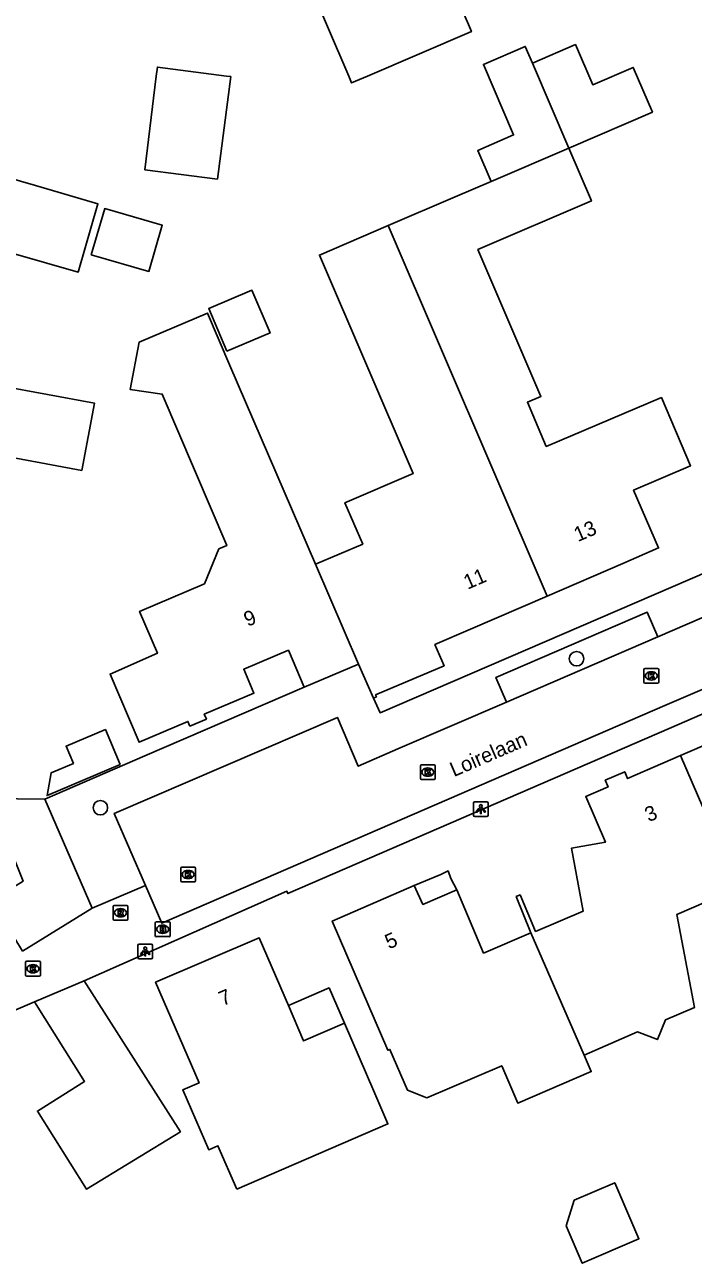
# Model space of a CAD drawing. Extents: x 157767 to 159171, y 387842 to 389425.
# Drawn here: x 158081 to 158126.1, y 388669.8 to 388753.5 of the extents above; entities that cross this region are included whole.
import ezdxf

# ---------------------------------------------------------------- set-up
doc = ezdxf.new("R2010")
doc.units = 0
for name, color, linetype in [('IMGEO_Boom', 7, 'Continuous'), ('IMGEO_Brandkraan', 7, 'Continuous'), ('IMGEO_Kolk', 7, 'Continuous'), ('IMGEO_Lichtpunt', 7, 'Continuous'), ('IMGEO_Openbare_ruimte_label', 7, 'Continuous'), ('IMGEO_Pand', 7, 'Continuous'), ('IMGEO_Pand_nummerreeks', 7, 'Continuous'), ('IMGEO_Pand_overbouw', 7, 'Continuous'), ('IMGEO_Rijbaan_lokaal_open', 7, 'Continuous'), ('IMGEO_Rioolput', 7, 'Continuous'), ('IMGEO_Voetpad_open', 7, 'Continuous')]:
    doc.layers.add(name, color=color, linetype=linetype)

msp = doc.modelspace()

# ---------------------------------------------------------------- linework, layer by layer
at = {"layer": 'IMGEO_Boom'}
for centre in [(158118.262, 388710.655), (158086.105, 388700.597)]:
    msp.add_circle(centre, 0.489, dxfattribs=at)
at = {"layer": 'IMGEO_Brandkraan'}
for p, q in [((158089.813, 388691.961), (158089.813, 388692.813)), ((158089.888, 388692.887), (158090.74, 388692.887)), ((158090.324, 388692.107), (158090.299, 388692.107)), ((158090.301, 388692.667), (158090.326, 388692.667)), ((158090.814, 388692.813), (158090.814, 388691.961)), ((158090.74, 388691.887), (158089.888, 388691.887))]:
    msp.add_line(p, q, dxfattribs=at)
for points in [[(158089.813, 388691.961), (158089.813, 388692.813)], [(158089.888, 388692.887), (158090.74, 388692.887)], [(158090.161, 388692.587), (158090.161, 388692.187), (158090.374, 388692.187)], [(158090.392, 388692.587), (158090.161, 388692.587)], [(158090.34, 388692.506), (158090.286, 388692.506), (158090.286, 388692.43)], [(158090.286, 388692.43), (158090.339, 388692.43)], [(158090.348, 388692.354), (158090.286, 388692.354), (158090.286, 388692.273)], [(158090.286, 388692.273), (158090.348, 388692.273)], [(158090.814, 388692.813), (158090.814, 388691.961)], [(158090.74, 388691.887), (158089.888, 388691.887)]]:
    msp.add_lwpolyline(points, dxfattribs=at)
for centre, radius, start, end in [((158089.89, 388692.811), 0.0765, 91.55205, 178.44795), ((158089.89, 388692.811), 0.0765, 91.55205, 178.44795), ((158090.341, 388692.468), 0.0379, 267.82845, 90.93552), ((158090.349, 388692.313), 0.0404, 269.87594, 90.50774), ((158090.38, 388692.438), 0.251, 268.66757, 293.53466), ((158090.396, 388692.442), 0.145, 59.4692, 91.53667), ((158090.421, 388692.489), 0.0922, 285.51372, 58.15012), ((158090.426, 388692.297), 0.105, 301.31148, 78.98903), ((158090.738, 388692.811), 0.0765, 1.55205, 88.44795), ((158090.738, 388692.811), 0.0765, 1.55205, 88.44795), ((158089.89, 388691.963), 0.0765, 181.55205, 268.44795), ((158089.89, 388691.963), 0.0765, 181.55205, 268.44795), ((158090.738, 388691.963), 0.0765, 271.55205, 358.44795), ((158090.738, 388691.963), 0.0765, 271.55205, 358.44795)]:
    msp.add_arc(centre, radius, start, end, dxfattribs=at)
for centre, major_axis, ratio, start_param, end_param in [((158090.3, 388692.387), (-0.387, 0.002), 0.722429, 4.712389, 7.853982), ((158090.325, 388692.387), (-0.39, 0.002), 0.717154, 1.570796, 4.712389)]:
    msp.add_ellipse(centre, major_axis=major_axis, ratio=ratio, start_param=start_param, end_param=end_param, dxfattribs=at)
at = {"layer": 'IMGEO_Kolk'}
for p, q in [((158122.81, 388709.072), (158122.81, 388709.924)), ((158122.885, 388709.998), (158123.737, 388709.998)), ((158123.298, 388709.778), (158123.323, 388709.778)), ((158123.811, 388709.924), (158123.811, 388709.072)), ((158123.737, 388708.998), (158122.885, 388708.998)), ((158123.321, 388709.218), (158123.296, 388709.218)), ((158107.713, 388702.572), (158107.713, 388703.424)), ((158107.788, 388703.498), (158108.64, 388703.498)), ((158108.201, 388703.278), (158108.226, 388703.278)), ((158108.714, 388703.424), (158108.714, 388702.572)), ((158108.64, 388702.498), (158107.788, 388702.498)), ((158108.224, 388702.718), (158108.199, 388702.718)), ((158091.526, 388695.66), (158091.526, 388696.512)), ((158091.601, 388696.586), (158092.453, 388696.586)), ((158092.014, 388696.366), (158092.039, 388696.366)), ((158092.527, 388696.512), (158092.527, 388695.66)), ((158092.453, 388695.586), (158091.601, 388695.586)), ((158092.037, 388695.806), (158092.012, 388695.806)), ((158081.053, 388689.296), (158081.053, 388690.148)), ((158081.128, 388690.222), (158081.98, 388690.222)), ((158081.541, 388690.002), (158081.566, 388690.002)), ((158082.054, 388690.148), (158082.054, 388689.296)), ((158081.98, 388689.222), (158081.128, 388689.222)), ((158081.564, 388689.442), (158081.539, 388689.442))]:
    msp.add_line(p, q, dxfattribs=at)
for points in [[(158122.81, 388709.072), (158122.81, 388709.924)], [(158122.885, 388709.998), (158123.737, 388709.998)], [(158123.131, 388709.698), (158123.254, 388709.698), (158123.254, 388709.547), (158123.384, 388709.698), (158123.548, 388709.698), (158123.402, 388709.547), (158123.555, 388709.298), (158123.403, 388709.298), (158123.318, 388709.462), (158123.254, 388709.395), (158123.254, 388709.298), (158123.131, 388709.298), (158123.131, 388709.698)], [(158123.811, 388709.924), (158123.811, 388709.072)], [(158123.737, 388708.998), (158122.885, 388708.998)], [(158107.713, 388702.572), (158107.713, 388703.424)], [(158107.788, 388703.498), (158108.64, 388703.498)], [(158108.034, 388703.198), (158108.157, 388703.198), (158108.157, 388703.047), (158108.287, 388703.198), (158108.451, 388703.198), (158108.305, 388703.047), (158108.458, 388702.798), (158108.306, 388702.798), (158108.221, 388702.962), (158108.157, 388702.895), (158108.157, 388702.798), (158108.034, 388702.798), (158108.034, 388703.198)], [(158108.714, 388703.424), (158108.714, 388702.572)], [(158108.64, 388702.498), (158107.788, 388702.498)], [(158091.526, 388695.66), (158091.526, 388696.512)], [(158091.601, 388696.586), (158092.453, 388696.586)], [(158091.847, 388696.286), (158091.97, 388696.286), (158091.97, 388696.135), (158092.1, 388696.286), (158092.264, 388696.286), (158092.118, 388696.135), (158092.271, 388695.886), (158092.119, 388695.886), (158092.034, 388696.05), (158091.97, 388695.983), (158091.97, 388695.886), (158091.847, 388695.886), (158091.847, 388696.286)], [(158092.527, 388696.512), (158092.527, 388695.66)], [(158092.453, 388695.586), (158091.601, 388695.586)], [(158081.053, 388689.296), (158081.053, 388690.148)], [(158081.128, 388690.222), (158081.98, 388690.222)], [(158081.374, 388689.922), (158081.497, 388689.922), (158081.497, 388689.771), (158081.627, 388689.922), (158081.791, 388689.922), (158081.645, 388689.771), (158081.798, 388689.522), (158081.646, 388689.522), (158081.561, 388689.686), (158081.497, 388689.619), (158081.497, 388689.522), (158081.374, 388689.522), (158081.374, 388689.922)], [(158082.054, 388690.148), (158082.054, 388689.296)], [(158081.98, 388689.222), (158081.128, 388689.222)]]:
    msp.add_lwpolyline(points, dxfattribs=at)
for centre, start, end in [((158122.887, 388709.922), 91.55205, 178.44795), ((158122.887, 388709.922), 91.55205, 178.44795), ((158123.735, 388709.922), 1.55205, 88.44795), ((158123.735, 388709.922), 1.55205, 88.44795), ((158122.887, 388709.074), 181.55205, 268.44795), ((158122.887, 388709.074), 181.55205, 268.44795), ((158123.735, 388709.074), 271.55205, 358.44795), ((158123.735, 388709.074), 271.55205, 358.44795), ((158107.79, 388703.422), 91.55205, 178.44795), ((158107.79, 388703.422), 91.55205, 178.44795), ((158108.638, 388703.422), 1.55205, 88.44795), ((158108.638, 388703.422), 1.55205, 88.44795), ((158107.79, 388702.574), 181.55205, 268.44795), ((158107.79, 388702.574), 181.55205, 268.44795), ((158108.638, 388702.574), 271.55205, 358.44795), ((158108.638, 388702.574), 271.55205, 358.44795), ((158091.603, 388696.51), 91.55205, 178.44795), ((158091.603, 388696.51), 91.55205, 178.44795), ((158092.451, 388696.51), 1.55205, 88.44795), ((158092.451, 388696.51), 1.55205, 88.44795), ((158091.603, 388695.662), 181.55205, 268.44795), ((158091.603, 388695.662), 181.55205, 268.44795), ((158092.451, 388695.662), 271.55205, 358.44795), ((158092.451, 388695.662), 271.55205, 358.44795), ((158081.13, 388690.146), 91.55205, 178.44795), ((158081.13, 388690.146), 91.55205, 178.44795), ((158081.978, 388690.146), 1.55205, 88.44795), ((158081.978, 388690.146), 1.55205, 88.44795), ((158081.13, 388689.298), 181.55205, 268.44795), ((158081.13, 388689.298), 181.55205, 268.44795), ((158081.978, 388689.298), 271.55205, 358.44795), ((158081.978, 388689.298), 271.55205, 358.44795)]:
    msp.add_arc(centre, 0.0765, start, end, dxfattribs=at)
for centre, major_axis, ratio, start_param, end_param in [((158123.297, 388709.498), (-0.387, 0.002), 0.722429, 4.712389, 7.853982), ((158123.322, 388709.498), (-0.39, 0.002), 0.717154, 1.570796, 4.712389), ((158108.2, 388702.998), (-0.387, 0.002), 0.722429, 4.712389, 7.853982), ((158108.225, 388702.998), (-0.39, 0.002), 0.717154, 1.570796, 4.712389), ((158092.013, 388696.086), (-0.387, 0.002), 0.722429, 4.712389, 7.853982), ((158092.038, 388696.086), (-0.39, 0.002), 0.717154, 1.570796, 4.712389), ((158081.54, 388689.722), (-0.387, 0.002), 0.722429, 4.712389, 7.853982), ((158081.565, 388689.722), (-0.39, 0.002), 0.717154, 1.570796, 4.712389)]:
    msp.add_ellipse(centre, major_axis=major_axis, ratio=ratio, start_param=start_param, end_param=end_param, dxfattribs=at)
at = {"layer": 'IMGEO_Lichtpunt'}
for p, q in [((158111.297, 388700.905), (158111.297, 388700.098)), ((158111.297, 388700.905), (158111.297, 388700.098)), ((158112.199, 388701), (158111.391, 388701)), ((158112.199, 388701), (158111.391, 388701)), ((158112.293, 388700.098), (158112.293, 388700.905)), ((158112.293, 388700.098), (158112.293, 388700.905)), ((158111.391, 388700.004), (158112.199, 388700.004)), ((158111.391, 388700.004), (158112.199, 388700.004)), ((158088.635, 388691.293), (158088.635, 388690.486)), ((158088.635, 388691.293), (158088.635, 388690.486)), ((158089.537, 388691.388), (158088.729, 388691.388)), ((158089.537, 388691.388), (158088.729, 388691.388)), ((158089.631, 388690.486), (158089.631, 388691.293)), ((158089.631, 388690.486), (158089.631, 388691.293)), ((158088.729, 388690.392), (158089.537, 388690.392)), ((158088.729, 388690.392), (158089.537, 388690.392))]:
    msp.add_line(p, q, dxfattribs=at)
for points in [[(158111.671, 388700.569), (158111.71, 388700.541), (158111.522, 388700.279), (158111.484, 388700.306), (158111.671, 388700.569)], [(158111.773, 388700.521), (158111.82, 388700.521), (158111.82, 388700.199), (158111.773, 388700.199), (158111.773, 388700.521)], [(158111.883, 388700.541), (158111.921, 388700.568), (158112.108, 388700.306), (158112.069, 388700.278), (158111.883, 388700.541)], [(158089.009, 388690.957), (158089.048, 388690.929), (158088.86, 388690.667), (158088.822, 388690.694), (158089.009, 388690.957)], [(158089.111, 388690.909), (158089.158, 388690.909), (158089.158, 388690.587), (158089.111, 388690.587), (158089.111, 388690.909)], [(158089.221, 388690.929), (158089.259, 388690.956), (158089.446, 388690.694), (158089.407, 388690.666), (158089.221, 388690.929)]]:
    msp.add_lwpolyline(points, dxfattribs=at)
for centre in [(158111.796, 388700.703), (158089.134, 388691.091)]:
    msp.add_circle(centre, 0.0994, dxfattribs=at)
for centre, start, end in [((158111.391, 388700.905), 90, 180), ((158111.391, 388700.905), 90, 180), ((158112.199, 388700.905), 0, 90), ((158112.199, 388700.905), 0, 90), ((158111.391, 388700.098), 180, 270), ((158111.391, 388700.098), 180, 270), ((158112.199, 388700.098), 270, 0), ((158112.199, 388700.098), 270, 360), ((158088.729, 388691.293), 90, 180), ((158088.729, 388691.293), 90, 180), ((158089.537, 388691.293), 0, 90), ((158089.537, 388691.293), 0, 90), ((158088.729, 388690.486), 180, 270), ((158088.729, 388690.486), 180, 270), ((158089.537, 388690.486), 270, 0), ((158089.537, 388690.486), 270, 360)]:
    msp.add_arc(centre, 0.0946, start, end, dxfattribs=at)
at = {"layer": 'IMGEO_Pand'}
for points in [[(158102.873, 388750), (158100.069, 388756.563), (158098.104, 388761.16), (158106.19, 388764.627), (158108.155, 388760.03), (158111.161, 388752.999), (158104.146, 388750), (158103.07, 388749.54), (158102.873, 388750)], [(158112.491, 388742.885), (158111.59, 388744.985), (158114.013, 388746.025), (158111.968, 388750.789), (158114.793, 388752.001), (158115.277, 388750.873)], [(158117.739, 388745.138), (158123.389, 388747.563), (158122.092, 388750.584), (158119.355, 388749.409), (158118.19, 388752.124), (158115.277, 388750.873)], [(158094.007, 388743.039), (158089.104, 388743.671), (158089.878, 388750), (158089.952, 388750.606), (158094.628, 388750), (158094.906, 388749.964), (158094.007, 388743.039)], [(158115.277, 388750.873), (158117.739, 388745.138)], [(158075.789, 388744.331), (158081.72, 388742.6), (158085.94, 388741.382), (158084.606, 388736.762), (158080.38, 388737.98), (158073.565, 388739.944), (158071.86, 388734.03), (158067.254, 388735.368), (158062.452, 388736.763), (158064.588, 388744.125), (158069.289, 388742.786), (158070.191, 388745.965)], [(158117.739, 388745.138), (158119.269, 388741.573), (158111.6, 388738.281), (158115.856, 388728.369), (158114.939, 388727.976), (158116.218, 388724.995), (158123.988, 388728.285), (158125.961, 388723.69), (158122.118, 388722.028), (158123.799, 388718.137), (158121.38, 388717.092), (158116.266, 388714.882)], [(158112.491, 388742.885), (158117.739, 388745.138)], [(158105.536, 388739.9), (158110.07, 388741.846), (158112.491, 388742.885)], [(158085.492, 388737.926), (158086.394, 388741.049), (158090.278, 388739.928), (158089.376, 388736.804), (158085.492, 388737.926)], [(158100.638, 388717.032), (158103.821, 388718.399), (158102.623, 388721.188), (158107.223, 388723.163), (158100.895, 388737.907), (158105.536, 388739.9)], [(158116.266, 388714.882), (158105.536, 388739.9)], [(158094.649, 388731.415), (158093.42, 388734.302), (158096.332, 388735.542), (158097.562, 388732.655), (158094.649, 388731.415)], [(158099.864, 388708.724), (158098.797, 388711.231), (158095.786, 388709.949), (158096.472, 388708.336), (158093.121, 388706.91), (158093.26, 388706.584), (158092.145, 388706.11), (158092.013, 388706.419), (158088.715, 388705.015), (158086.757, 388709.616), (158089.955, 388711.021), (158088.752, 388713.848), (158093.135, 388715.713), (158094.113, 388718.07), (158094.636, 388718.293), (158090.283, 388728.521), (158088.117, 388728.826), (158088.715, 388732.029), (158093.346, 388734), (158094.851, 388730.465), (158100.638, 388717.032)], [(158084.862, 388723.375), (158074.95, 388725.205), (158074.636, 388723.504), (158072.511, 388723.897), (158072.164, 388721.947), (158070.4, 388722.259), (158069.578, 388717.73), (158063.701, 388718.771), (158058.777, 388719.644), (158059.718, 388725.009), (158059.233, 388725.097), (158059.43, 388726.184), (158059.91, 388726.139), (158060.281, 388728.104), (158064.478, 388727.37), (158068.338, 388726.695), (158068.912, 388729.966), (158073.83, 388729.06), (158075.984, 388728.664), (158076.171, 388729.677), (158085.7, 388727.918), (158084.862, 388723.375)], [(158100.638, 388717.032), (158103.54, 388710.289)], [(158116.266, 388714.882), (158111.105, 388712.651), (158108.695, 388711.61), (158109.311, 388710.185), (158104.688, 388708.207), (158104.74, 388708.086), (158104.538, 388707.998)], [(158103.54, 388710.289), (158099.864, 388708.724)], [(158104.538, 388707.998), (158103.54, 388710.289)], [(158125.29, 388704.111), (158131.722, 388706.892), (158133.025, 388703.88), (158134.76, 388705.224), (158137.384, 388701.72), (158138.161, 388702.047), (158141.725, 388693.793), (158137.134, 388691.813), (158137.012, 388691.76), (158133.205, 388696.905), (158129.155, 388695.158)], [(158087.445, 388703.511), (158082.505, 388701.409), (158082.778, 388702.948), (158084.28, 388703.587), (158083.789, 388704.741), (158086.441, 388705.87), (158087.445, 388703.511)], [(158115.18, 388692.14), (158114.187, 388694.593), (158114.445, 388694.704), (158115.499, 388692.24), (158118.718, 388693.616), (158118.373, 388695.432), (158117.913, 388697.858), (158120.209, 388698.259), (158118.883, 388701.343), (158120.395, 388701.997), (158120.196, 388702.454), (158121.516, 388703.024), (158121.713, 388702.565), (158125.29, 388704.111)], [(158125.29, 388704.111), (158129.155, 388695.158)], [(158080.844, 388690.903), (158078.758, 388694.328), (158080.894, 388695.642), (158078.643, 388701.212), (158082.352, 388701.179)], [(158082.352, 388701.179), (158085.544, 388693.809)], [(158118.771, 388683.89), (158119.254, 388682.78), (158114.293, 388680.646), (158113.207, 388683.171), (158108.155, 388680.998), (158106.841, 388681.521), (158105.655, 388684.277), (158105.518, 388684.218), (158103.746, 388688.338), (158101.767, 388692.936), (158107.303, 388695.343), (158107.881, 388694.066), (158110.173, 388695.046), (158111.985, 388690.78), (158115.18, 388692.14)], [(158129.155, 388695.158), (158125.044, 388693.385), (158126.228, 388687.108), (158124.266, 388686.261), (158123.726, 388684.941), (158122.386, 388685.45), (158118.771, 388683.89)], [(158085.544, 388693.809), (158080.844, 388690.903)], [(158118.771, 388683.89), (158115.18, 388692.14)], [(158095.316, 388674.833), (158094.046, 388677.769), (158093.417, 388677.497), (158091.668, 388681.535), (158092.77, 388682.012), (158089.83, 388688.804), (158096.82, 388691.812), (158098.798, 388687.236), (158099.829, 388684.85), (158102.583, 388686.04), (158104.568, 388681.451), (158105.521, 388679.247), (158100.839, 388677.222), (158095.316, 388674.833)], [(158085.01, 388688.91), (158091.509, 388678.715), (158085.166, 388674.846), (158081.85, 388680.104), (158085.035, 388682.113), (158081.65, 388687.48)], [(158081.65, 388687.48), (158085.01, 388688.91)], [(158117.556, 388672.359), (158118.108, 388674.093), (158120.838, 388675.269), (158122.469, 388671.483), (158118.644, 388669.835), (158117.556, 388672.359)]]:
    msp.add_lwpolyline(points, dxfattribs=at)
at = {"layer": 'IMGEO_Pand_overbouw'}
for points in [[(158107.303, 388695.343), (158107.881, 388694.066), (158110.173, 388695.046), (158109.782, 388695.822), (158109.581, 388696.326), (158109.096, 388696.091)], [(158098.798, 388687.236), (158099.829, 388684.85), (158102.583, 388686.04), (158101.552, 388688.426)]]:
    msp.add_lwpolyline(points, close=True, dxfattribs=at)
at = {"layer": 'IMGEO_Rijbaan_lokaal_open'}
for points in [[(158123.746, 388712.134), (158142.573, 388720.269)], [(158123.746, 388712.134), (158113.525, 388707.726)], [(158089.145, 388695.349), (158090.25, 388692.79), (158124.222, 388707.486), (158134.627, 388711.957)], [(158089.145, 388695.349), (158087.045, 388700.215), (158102.109, 388706.697), (158103.519, 388703.4), (158106.201, 388704.567), (158113.525, 388707.726)]]:
    msp.add_lwpolyline(points, dxfattribs=at)
at = {"layer": 'IMGEO_Rioolput'}
for p, q in [((158086.966, 388693.076), (158086.966, 388693.928)), ((158087.041, 388694.002), (158087.893, 388694.002)), ((158087.454, 388693.782), (158087.479, 388693.782)), ((158087.967, 388693.928), (158087.967, 388693.076)), ((158087.893, 388693.002), (158087.041, 388693.002)), ((158087.477, 388693.222), (158087.452, 388693.222))]:
    msp.add_line(p, q, dxfattribs=at)
for points in [[(158086.966, 388693.076), (158086.966, 388693.928)], [(158087.041, 388694.002), (158087.893, 388694.002)], [(158087.967, 388693.928), (158087.967, 388693.076)], [(158087.893, 388693.002), (158087.041, 388693.002)], [(158087.555, 388693.7), (158087.303, 388693.702), (158087.303, 388693.302)], [(158087.303, 388693.302), (158087.427, 388693.302), (158087.427, 388693.464), (158087.438, 388693.464)], [(158087.481, 388693.621), (158087.427, 388693.621), (158087.427, 388693.54)], [(158087.427, 388693.54), (158087.479, 388693.54)], [(158087.485, 388693.435), (158087.556, 388693.302), (158087.696, 388693.302), (158087.631, 388693.428)]]:
    msp.add_lwpolyline(points, dxfattribs=at)
for centre, radius, start, end in [((158087.043, 388693.926), 0.0765, 91.55205, 178.44795), ((158087.043, 388693.926), 0.0765, 91.55205, 178.44795), ((158087.891, 388693.926), 0.0765, 1.55205, 88.44795), ((158087.891, 388693.926), 0.0765, 1.55205, 88.44795), ((158087.043, 388693.078), 0.0765, 181.55205, 268.44795), ((158087.043, 388693.078), 0.0765, 181.55205, 268.44795), ((158087.437, 388693.411), 0.0533, 26.02933, 88.69889), ((158087.463, 388693.729), 0.19, 274.7715, 282.96867), ((158087.487, 388693.525), 0.0964, 77.00612, 93.18647), ((158087.501, 388693.582), 0.0378, 276.66336, 79.67722), ((158087.554, 388693.59), 0.109, 350.36119, 89.41601), ((158087.552, 388693.59), 0.112, 277.58423, 350.98172), ((158087.536, 388693.375), 0.108, 29.51342, 73.79051), ((158087.891, 388693.078), 0.0765, 271.55205, 358.44795), ((158087.891, 388693.078), 0.0765, 271.55205, 358.44795)]:
    msp.add_arc(centre, radius, start, end, dxfattribs=at)
for centre, major_axis, ratio, start_param, end_param in [((158087.453, 388693.502), (-0.387, 0.002), 0.722429, 4.712389, 7.853982), ((158087.478, 388693.502), (-0.39, 0.002), 0.717154, 1.570796, 4.712389)]:
    msp.add_ellipse(centre, major_axis=major_axis, ratio=ratio, start_param=start_param, end_param=end_param, dxfattribs=at)
at = {"layer": 'IMGEO_Voetpad_open'}
for points in [[(158104.538, 388707.998), (158104.988, 388707.005), (158155.532, 388728.793)], [(158113.525, 388707.726), (158112.815, 388709.389), (158123.035, 388713.795), (158123.746, 388712.134)], [(158134.614, 388710.329), (158124.506, 388705.952), (158098.771, 388694.795), (158098.704, 388694.959), (158085.01, 388688.91)], [(158082.352, 388701.179), (158089.109, 388704.09), (158099.864, 388708.724)], [(158085.544, 388693.809), (158089.145, 388695.349)], [(158081.65, 388687.48), (158078.988, 388686.371), (158068.943, 388680.157)]]:
    msp.add_lwpolyline(points, dxfattribs=at)

# ---------------------------------------------------------------- texts
at = {"layer": 'IMGEO_Openbare_ruimte_label'}
msp.add_text('Loirelaan', height=1, rotation=23.38664, dxfattribs=at).set_placement((158109.977, 388702.656))
at = {"layer": 'IMGEO_Pand_nummerreeks'}
for s, rotation, p in [('13', 23.37095, (158118.348, 388718.526)), ('11', 23.37095, (158110.901, 388715.309)), ('9', 23.06295, (158096.051, 388712.801)), ('3', 23.36567, (158123.135, 388699.607)), ('5', 23.49894, (158105.59, 388691.022)), ('7', 23.28361, (158094.369, 388687.186))]:
    msp.add_text(s, height=1, rotation=rotation, dxfattribs=at).set_placement(p)

doc.saveas('drawing.dxf')
